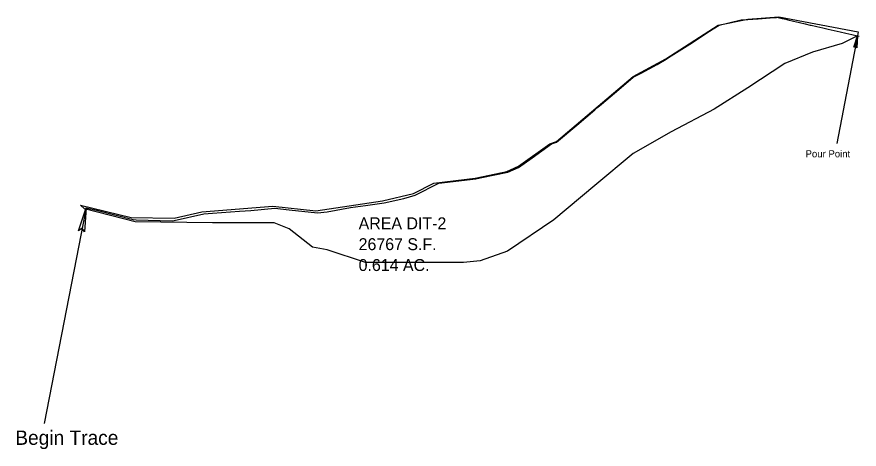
# Model space of a CAD drawing. Extents: x 2779 to 5445, y 2709 to 3371.
import ezdxf

# ---------------------------------------------------------------- set-up
doc = ezdxf.new("R2010")
doc.units = 0
for name, color, linetype in [('DESIGN - SCRATCH - User 1', 7, 'Continuous'), ('SURVEY - CENTERLINE - Preliminary', 7, 'Continuous'), ('SURVEY - CENTERLINE - Preliminary Text', 7, 'Continuous'), ('SURVEY - DRAINAGE - Area Shapes', 7, 'Continuous')]:
    doc.layers.add(name, color=color, linetype=linetype)

msp = doc.modelspace()

# ---------------------------------------------------------------- linework, layer by layer
at = {"layer": 'DESIGN - SCRATCH - User 1'}
msp.add_line((3484.95, 3056.09), (3467.42, 2965.64), dxfattribs=at)
msp.add_lwpolyline([(3484.95, 3056.09), (3484.26, 3045.98), (3483.28, 3047.5), (3481.76, 3046.47)], close=True, dxfattribs=at)
msp.add_lwpolyline([(3484.95, 3056.09), (3484.26, 3045.98), (3483.28, 3047.5), (3481.76, 3046.47), (3484.95, 3056.09)], dxfattribs=at)
at = {"layer": 'SURVEY - CENTERLINE - Preliminary'}
msp.add_lwpolyline([(2837.55, 2911.76), (2847.47, 2909.42), (2876.96, 2901.81), (2879.54, 2901.74), (2909.92, 2900.89), (2911.62, 2901.2), (2936.38, 2906.7), (2943.7, 2907.22), (2966.42, 2908.81), (2975.77, 2909.56), (2995.97, 2911.43), (3007.85, 2910.17), (3031.85, 2907.49), (3039.93, 2908.37), (3059.55, 2912.02), (3072.01, 2913.81), (3087.8, 2915.98), (3104.08, 2919.55), (3113.62, 2922.45), (3133.57, 2932.32), (3135.74, 2932.75), (3136.16, 2932.8), (3164.74, 2935.94), (3168.24, 2936.76), (3191.43, 2941.51), (3200.31, 2945.55), (3211.83, 2953.59), (3228.17, 2965.51), (3231.52, 2966.41), (3232.39, 2966.84), (3249.31, 2981.18), (3264.47, 2994.04), (3266.95, 2996.13), (3269.96, 2998.69), (3284.57, 3011.08), (3296.54, 3021.34), (3303.47, 3024.72), (3316.84, 3031.88), (3324.34, 3036.32), (3328.62, 3039.26), (3344.16, 3048.99), (3360.7, 3059.88), (3363.78, 3061.88), (3368.89, 3065.07), (3386.05, 3069.08), (3386.86, 3069.27), (3387.55, 3069.4), (3387.86, 3069.46), (3388.49, 3069.5), (3391.61, 3069.7), (3392.78, 3069.78), (3401.37, 3070.33), (3411.71, 3071.04), (3417, 3071.45), (3417.01, 3071.46), (3417.01, 3071.46), (3417.03, 3071.47), (3417.31, 3071.6), (3421.55, 3070.6), (3424.85, 3069.83), (3426.42, 3069.46), (3431.1, 3068.37), (3431.29, 3068.32), (3436.16, 3067.18), (3441.04, 3066.03), (3445.15, 3065.07), (3445.91, 3064.89), (3450.78, 3063.76), (3455.66, 3062.63), (3456.93, 3062.35), (3460.27, 3061.61), (3470.31, 3059.38), (3475.19, 3058.28), (3480.07, 3057.19), (3484.95, 3056.09), (3486.24, 3055.83)], dxfattribs=at)
at = {"layer": 'SURVEY - CENTERLINE - Preliminary Text'}
msp.add_line((2837.55, 2911.76), (2802.49, 2730.87), dxfattribs=at)
msp.add_lwpolyline([(2837.55, 2911.76), (2836.18, 2891.56), (2834.22, 2894.58), (2831.17, 2892.53)], close=True, dxfattribs=at)
msp.add_lwpolyline([(2837.55, 2911.76), (2836.18, 2891.56), (2834.22, 2894.58), (2831.17, 2892.53), (2837.55, 2911.76)], dxfattribs=at)
at = {"layer": 'SURVEY - DRAINAGE - Area Shapes'}
for points in [[(3030.29, 2909.1), (3086.33, 2917.5), (3112.24, 2923.88), (3129.3, 2932.32), (3164.05, 2936.65), (3190.73, 2942.24), (3200.31, 2946.6), (3226.71, 2965.51), (3232.39, 2967.3), (3296.54, 3021.8), (3324.01, 3036.65), (3368, 3065.07), (3392.78, 3069.96), (3418.91, 3071.91)], [(3418.91, 3071.91), (3485.45, 3059.29), (3484.95, 3056.09)], [(3484.95, 3056.09), (3471.93, 3049.55), (3446.98, 3042.18), (3423.88, 3032.88), (3392.78, 3012.49), (3364.67, 2994.58), (3328.62, 2975.43), (3296.54, 2957.27), (3264.47, 2930.4), (3230.01, 2901.59), (3191.27, 2875.3), (3168.24, 2867.29), (3154.26, 2865.94), (3072.01, 2865.94), (3039.93, 2876.62), (3027.7, 2878.6), (3007.85, 2894.22), (2995.32, 2899.13), (2943.7, 2899.13), (2878.66, 2900.05), (2836.23, 2910.76), (2833, 2914.1)], [(2833, 2914.1), (2875.33, 2903.49), (2911.62, 2903.17), (2934.81, 2908.32), (2994.41, 2913.04), (3030.29, 2909.1)]]:
    msp.add_lwpolyline(points, dxfattribs=at)

# ---------------------------------------------------------------- texts
at = {"layer": 'DESIGN - SCRATCH - User 1'}
msp.add_text('Pour Point', height=6, dxfattribs=at).set_placement((3441.29, 2954.04))
at = {"layer": 'SURVEY - CENTERLINE - Preliminary Text'}
msp.add_text('Begin Trace ', height=12, dxfattribs=at).set_placement((2778.17, 2712.94))
at = {"layer": 'SURVEY - DRAINAGE - Area Shapes'}
for s, p in [('AREA DIT-2', (3066.28, 2893.74)), ('26767 S.F.', (3066.28, 2876.24)), ('0.614 AC.', (3066.28, 2858.74))]:
    msp.add_text(s, height=10, dxfattribs=at).set_placement(p)

doc.saveas('drawing.dxf')
